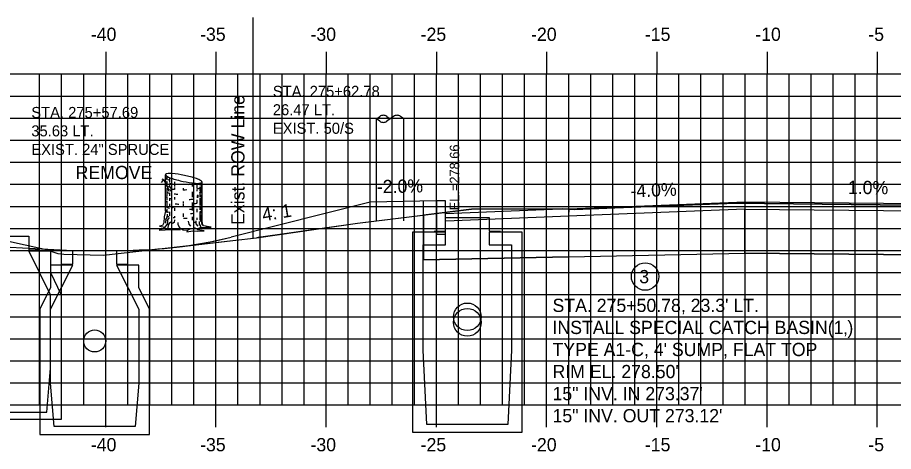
# Model space of a CAD drawing. Extents: x 853563 to 853733, y 366268 to 366378.
# Drawn here: x 853601.77 to 853641.5, y 366300.13 to 366319.79 of the extents above; entities that cross this region are included whole.
import ezdxf

# ---------------------------------------------------------------- set-up
doc = ezdxf.new("R2010")
doc.units = 0
for name, color, linetype in [('ANNOTATION', 7, 'Continuous'), ('D_Curb_Type1_Lt', 7, 'Continuous'), ('D_Drainage_CB_TypeA1-B1', 7, 'Continuous'), ('D_Drainage_Text', 7, 'Continuous'), ('D_Roadway_Edge_TW', 7, 'Continuous'), ('D_Roadway_FinishedGrade', 7, 'Continuous'), ('D_Roadway_SubGrade', 7, 'Continuous'), ('D_Text_Monospaced', 7, 'Continuous'), ('D_Text_Standard', 7, 'Continuous'), ('E_ROW_Line', 7, 'Continuous'), ('H_V ANNOTATION', 7, 'Continuous'), ('JUNK COM EXC', 7, 'Continuous'), ('JUNK FILL', 7, 'Continuous'), ('MAJOR', 7, 'Continuous'), ('MINOR', 7, 'Continuous'), ('PDRAIN', 7, 'Continuous'), ('S_Drainage_CB', 7, 'Continuous'), ('S_Roadway_Centerline', 7, 'Continuous'), ('S_Trees_Conifer_Pay', 7, 'Continuous'), ('S_Utilities_Pole_Power', 7, 'Continuous')]:
    doc.layers.add(name, color=color, linetype=linetype)

msp = doc.modelspace()

# ---------------------------------------------------------------- linework, layer by layer
at = {"layer": 'D_Curb_Type1_Lt'}
msp.add_lwpolyline([(853620.77, 366311.482), (853620.77, 366309.982), (853621.187, 366309.982), (853621.187, 366311.482)], close=True, dxfattribs=at)
at = {"layer": 'D_Drainage_CB_TypeA1-B1'}
for p, q in [((853620.169, 366310.067), (853619.677, 366310.067)), ((853619.677, 366310.067), (853619.677, 366300.996)), ((853621.187, 366310.067), (853620.169, 366310.067)), ((853624.172, 366310.067), (853623.155, 366310.067)), ((853624.664, 366310.067), (853624.172, 366310.067)), ((853624.664, 366300.996), (853624.664, 366310.067)), ((853603.266, 366308.571), (853603.266, 366307.554)), ((853603.266, 366306.57), (853604.283, 366308.571)), ((853604.283, 366308.571), (853603.266, 366308.571)), ((853607.269, 366308.571), (853606.252, 366308.571)), ((853606.252, 366308.571), (853607.269, 366306.57)), ((853607.269, 366307.554), (853607.269, 366308.571)), ((853620.169, 366304.719), (853620.169, 366308.065)), ((853624.172, 366308.065), (853624.172, 366304.719)), ((853603.266, 366307.554), (853602.774, 366306.57)), ((853607.761, 366306.57), (853607.269, 366307.554)), ((853602.774, 366306.57), (853602.774, 366300.894)), ((853603.266, 366303.224), (853603.266, 366306.57)), ((853607.269, 366306.57), (853607.269, 366303.224)), ((853607.761, 366300.894), (853607.761, 366306.57)), ((853620.334, 366301.356), (853620.169, 366304.719)), ((853624.172, 366304.719), (853624.008, 366301.356)), ((853603.43, 366301.255), (853603.266, 366303.224)), ((853607.269, 366303.224), (853607.105, 366301.255)), ((853624.008, 366301.356), (853620.334, 366301.356)), ((853602.774, 366300.894), (853607.761, 366300.894)), ((853607.105, 366301.255), (853603.43, 366301.255)), ((853619.677, 366300.996), (853624.664, 366300.996))]:
    msp.add_line(p, q, dxfattribs=at)
for points in [[(853620.662, 366310.108), (853621.187, 366310.108), (853621.187, 366310.732), (853623.155, 366310.732), (853623.155, 366310.108), (853623.68, 366310.108)], [(853620.169, 366308.065), (853620.169, 366309.49), (853621.187, 366309.49), (853621.187, 366310.067)], [(853623.155, 366310.067), (853623.155, 366309.49), (853624.172, 366309.49), (853624.172, 366308.065)], [(853603.758, 366308.613), (853604.283, 366308.613), (853604.283, 366309.236), (853606.252, 366309.236), (853606.252, 366308.613), (853606.777, 366308.613)]]:
    msp.add_lwpolyline(points, dxfattribs=at)
at = {"layer": 'D_Drainage_Text'}
msp.add_circle((853630.235, 366308.056), 0.625, dxfattribs=at)
at = {"layer": 'D_Roadway_Edge_TW'}
for p, q in [((853626.768, 366311.122), (853621.187, 366310.899)), ((853626.768, 366311.122), (853626.758, 366310.789)), ((853626.781, 366310.789), (853621.2, 366310.565))]:
    msp.add_line(p, q, dxfattribs=at)
msp.add_lwpolyline([(853626.768, 366311.122), (853634.768, 366311.442), (853645.768, 366311.343), (853656.768, 366311.123), (853664.768, 366310.803)], dxfattribs=at)
at = {"layer": 'D_Roadway_FinishedGrade'}
for p, q in [((853617.77, 366311.422), (853611.462, 366309.845)), ((853599.411, 366309.486), (853604.283, 366309.236)), ((853606.252, 366309.236), (853607.011, 366309.252))]:
    msp.add_line(p, q, dxfattribs=at)
msp.add_lwpolyline([(853620.77, 366311.482), (853617.77, 366311.422)], dxfattribs=at)
msp.add_arc((853606.611, 366329.248), 20, 271.1458, 284.0362, dxfattribs=at)
at = {"layer": 'D_Roadway_SubGrade'}
for p, q in [((853620.187, 366308.817), (853620.187, 366311.47)), ((853626.758, 366308.949), (853620.187, 366308.817))]:
    msp.add_line(p, q, dxfattribs=at)
for points in [[(853634.758, 366311.109), (853626.758, 366310.789), (853626.758, 366308.949), (853634.758, 366309.109)], [(853634.758, 366309.109), (853634.758, 366311.109), (853645.758, 366311.01), (853656.758, 366310.79), (853656.758, 366308.79), (853645.758, 366309.01)]]:
    msp.add_lwpolyline(points, close=True, dxfattribs=at)
at = {"layer": 'E_ROW_Line'}
msp.add_line((853612.463, 366309.794), (853612.463, 366319.794), dxfattribs=at)
at = {"layer": 'JUNK COM EXC'}
msp.add_lwpolyline([(853620.187, 366310.842), (853620.187, 366308.817), (853626.758, 366308.949), (853634.758, 366309.109), (853645.758, 366309.01), (853656.758, 366308.79), (853665.758, 366308.61), (853665.766, 366310.621), (853661.346, 366310.741), (853659.822, 366310.792), (853658.471, 366310.84), (853657.772, 366310.858), (853645.768, 366311.281), (853644.236, 366311.274), (853640.891, 366311.31), (853634.333, 366311.383), (853628.855, 366311.175), (853627.053, 366311.098), (853626.465, 366311.121), (853622.365, 366311.115), (853620.187, 366310.842)], dxfattribs=at)
at = {"layer": 'JUNK FILL'}
msp.add_lwpolyline([(853609.359, 366309.437), (853611.54, 366309.683), (853612.606, 366309.811), (853617.194, 366310.468), (853620.77, 366310.915), (853620.77, 366311.482), (853617.77, 366311.422), (853611.462, 366309.845)], dxfattribs=at)
msp.add_arc((853606.611, 366329.248), 20, 277.8984, 284.0362, dxfattribs=at)
at = {"layer": 'MAJOR'}
for p, q in [((853605.768, 366318.238), (853605.768, 366317.236)), ((853610.768, 366318.238), (853610.768, 366317.236)), ((853615.768, 366318.238), (853615.768, 366317.236)), ((853620.768, 366318.238), (853620.768, 366317.236)), ((853625.768, 366318.238), (853625.768, 366317.236)), ((853630.768, 366318.238), (853630.768, 366317.236)), ((853635.768, 366318.238), (853635.768, 366317.236)), ((853640.768, 366318.238), (853640.768, 366317.236)), ((853575.768, 366317.236), (853715.768, 366317.236)), ((853575.768, 366317.236), (853715.768, 366317.236)), ((853605.768, 366302.236), (853605.768, 366317.236)), ((853610.768, 366302.236), (853610.768, 366317.236)), ((853615.768, 366302.236), (853615.768, 366317.236)), ((853620.768, 366302.236), (853620.768, 366317.236)), ((853625.768, 366302.236), (853625.768, 366317.236)), ((853630.768, 366302.236), (853630.768, 366317.236)), ((853635.768, 366302.236), (853635.768, 366317.236)), ((853640.768, 366302.236), (853640.768, 366317.236)), ((853575.768, 366312.236), (853715.768, 366312.236)), ((853575.768, 366307.236), (853715.768, 366307.236)), ((853575.768, 366302.236), (853715.768, 366302.236)), ((853575.768, 366302.236), (853715.768, 366302.236)), ((853605.768, 366301.234), (853605.768, 366302.236)), ((853610.768, 366301.234), (853610.768, 366302.236)), ((853615.768, 366301.234), (853615.768, 366302.236)), ((853620.768, 366301.234), (853620.768, 366302.236)), ((853625.768, 366301.234), (853625.768, 366302.236)), ((853630.768, 366301.234), (853630.768, 366302.236)), ((853635.768, 366301.234), (853635.768, 366302.236)), ((853640.768, 366301.234), (853640.768, 366302.236))]:
    msp.add_line(p, q, dxfattribs=at)
at = {"layer": 'MINOR'}
for p, q in [((853602.768, 366302.236), (853602.768, 366317.236)), ((853603.768, 366302.236), (853603.768, 366317.236)), ((853604.768, 366302.236), (853604.768, 366317.236)), ((853606.768, 366302.236), (853606.768, 366317.236)), ((853607.768, 366302.236), (853607.768, 366317.236)), ((853608.768, 366302.236), (853608.768, 366317.236)), ((853609.768, 366302.236), (853609.768, 366317.236)), ((853611.768, 366302.236), (853611.768, 366317.236)), ((853612.768, 366302.236), (853612.768, 366317.236)), ((853613.768, 366302.236), (853613.768, 366317.236)), ((853614.768, 366302.236), (853614.768, 366317.236)), ((853616.768, 366302.236), (853616.768, 366317.236)), ((853617.768, 366302.236), (853617.768, 366317.236)), ((853618.768, 366302.236), (853618.768, 366317.236)), ((853619.768, 366302.236), (853619.768, 366317.236)), ((853621.768, 366302.236), (853621.768, 366317.236)), ((853622.768, 366302.236), (853622.768, 366317.236)), ((853623.768, 366302.236), (853623.768, 366317.236)), ((853624.768, 366302.236), (853624.768, 366317.236)), ((853626.768, 366302.236), (853626.768, 366317.236)), ((853627.768, 366302.236), (853627.768, 366317.236)), ((853628.768, 366302.236), (853628.768, 366317.236)), ((853629.768, 366302.236), (853629.768, 366317.236)), ((853631.768, 366302.236), (853631.768, 366317.236)), ((853632.768, 366302.236), (853632.768, 366317.236)), ((853633.768, 366302.236), (853633.768, 366317.236)), ((853634.768, 366302.236), (853634.768, 366317.236)), ((853636.768, 366302.236), (853636.768, 366317.236)), ((853637.768, 366302.236), (853637.768, 366317.236)), ((853638.768, 366302.236), (853638.768, 366317.236)), ((853639.768, 366302.236), (853639.768, 366317.236)), ((853575.768, 366316.236), (853715.768, 366316.236)), ((853575.768, 366315.236), (853715.768, 366315.236)), ((853575.768, 366314.236), (853715.768, 366314.236)), ((853575.768, 366313.236), (853715.768, 366313.236)), ((853575.768, 366311.236), (853715.768, 366311.236)), ((853575.768, 366310.236), (853715.768, 366310.236)), ((853575.768, 366309.236), (853715.768, 366309.236)), ((853575.768, 366308.236), (853715.768, 366308.236)), ((853575.768, 366306.236), (853715.768, 366306.236)), ((853575.768, 366305.236), (853715.768, 366305.236)), ((853575.768, 366304.236), (853715.768, 366304.236)), ((853575.768, 366303.236), (853715.768, 366303.236))]:
    msp.add_line(p, q, dxfattribs=at)
at = {"layer": 'PDRAIN'}
for centre, radius in [((853622.171, 366306.231), 0.625), ((853622.171, 366305.981), 0.625), ((853622.171, 366305.981), 0.625), ((853605.268, 366305.136), 0.5)]:
    msp.add_circle(centre, radius, dxfattribs=at)
at = {"layer": 'S_Drainage_CB'}
for p, q in [((853602.277, 366309.224), (853603.261, 366309.224)), ((853603.261, 366307.223), (853602.277, 366309.224)), ((853603.261, 366309.224), (853603.261, 366308.24)), ((853603.261, 366308.24), (853603.753, 366307.223)), ((853603.261, 366303.909), (853603.261, 366307.223)), ((853603.753, 366307.223), (853603.753, 366301.58)), ((853603.097, 366301.908), (853603.261, 366303.909)), ((853599.423, 366301.908), (853603.097, 366301.908)), ((853603.753, 366301.58), (853598.766, 366301.58))]:
    msp.add_line(p, q, dxfattribs=at)
msp.add_lwpolyline([(853599.784, 366309.266), (853600.276, 366309.266), (853600.276, 366309.889), (853602.277, 366309.889), (853602.277, 366309.266), (853602.769, 366309.266)], dxfattribs=at)
at = {"layer": 'S_Roadway_Centerline'}
msp.add_lwpolyline([(853601.219, 366309.683), (853603, 366309.295), (853603.592, 366309.1), (853603.865, 366309.076), (853605.661, 366309.021), (853611.54, 366309.683), (853612.606, 366309.811), (853612.705, 366309.838), (853617.194, 366310.468), (853622.365, 366311.115), (853626.465, 366311.121), (853627.053, 366311.098), (853628.855, 366311.175), (853634.333, 366311.383), (853640.891, 366311.31), (853644.236, 366311.274)], dxfattribs=at)
at = {"layer": 'S_Trees_Conifer_Pay'}
for p, q in [((853608.475, 366311.024), (853608.475, 366312.671)), ((853608.546, 366312.599), (853608.546, 366312.436)), ((853608.664, 366312.538), (853608.664, 366312.315)), ((853608.546, 366312.369), (853608.546, 366312.241)), ((853608.546, 366312.054), (853608.546, 366311.718)), ((853608.607, 366312.043), (853608.658, 366311.984)), ((853608.664, 366312.226), (853608.664, 366312.179)), ((853608.892, 366312.342), (853608.892, 366312.142)), ((853608.892, 366312.085), (853608.892, 366311.996)), ((853609.282, 366312.068), (853609.282, 366311.973)), ((853609.688, 366312.3), (853609.688, 366312.132)), ((853609.908, 366312.279), (853609.908, 366312.047)), ((853610.033, 366312.287), (853610.033, 366312.19)), ((853610.033, 366312.115), (853610.033, 366311.911)), ((853610.092, 366312.298), (853610.092, 366311.827)), ((853610.139, 366310.614), (853610.139, 366312.336)), ((853608.546, 366311.681), (853608.546, 366311.518)), ((853608.664, 366311.844), (853608.664, 366311.712)), ((853608.892, 366311.648), (853608.892, 366311.543)), ((853609.688, 366311.895), (853609.688, 366311.658)), ((853609.908, 366312.006), (853609.908, 366311.932)), ((853610.033, 366311.854), (853610.033, 366311.654)), ((853610.092, 366311.763), (853610.092, 366311.455)), ((853608.546, 366311.471), (853608.546, 366311.255)), ((853608.664, 366311.601), (853608.664, 366311.491)), ((853608.664, 366311.356), (853608.664, 366311.214)), ((853609.282, 366311.455), (853609.282, 366311.38)), ((853609.282, 366311.356), (853609.282, 366311.207)), ((853609.688, 366311.413), (853609.688, 366311.261)), ((853609.908, 366311.529), (853609.908, 366311.39)), ((853610.033, 366311.607), (853610.033, 366311.271)), ((853610.092, 366311.407), (853610.092, 366310.915)), ((853608.546, 366311.224), (853608.546, 366311.15)), ((853608.546, 366311.109), (853608.546, 366310.936)), ((853608.664, 366310.987), (853608.664, 366310.814)), ((853608.892, 366311.176), (853608.892, 366311.03)), ((853609.282, 366310.915), (853609.282, 366310.762)), ((853609.688, 366311.218), (853609.688, 366311.045)), ((853609.908, 366311.119), (853609.908, 366310.977)), ((853610.033, 366311.218), (853610.033, 366311.082)), ((853610.033, 366310.983), (853610.033, 366310.604)), ((853610.092, 366310.861), (853610.092, 366310.614)), ((853608.892, 366310.798), (853608.892, 366310.709)), ((853609.688, 366310.767), (853609.688, 366310.614)), ((853609.908, 366310.715), (853609.908, 366310.621)), ((853609.471, 366310.157), (853609.597, 366310.221)), ((853609.908, 366310.221), (853609.745, 366310.285))]:
    msp.add_line(p, q, dxfattribs=at)
for points in [[(853608.658, 366312.169), (853608.621, 366312.095), (853608.574, 366312.152), (853608.516, 366312.22), (853608.424, 366312.414), (853608.359, 366312.461), (853608.328, 366312.468)], [(853608.429, 366312.402), (853608.353, 366312.41), (853608.281, 366312.311)], [(853608.643, 366311.916), (853608.607, 366312.043), (853608.543, 366312.159), (853608.512, 366312.226), (853608.443, 366312.373)], [(853608.691, 366312.132), (853608.722, 366312.047), (853608.726, 366311.98), (853608.695, 366311.916)], [(853609.96, 366311.642), (853609.966, 366311.737), (853609.922, 366311.714), (853609.922, 366311.619)], [(853608.821, 366311.243), (853608.808, 366311.166), (853608.761, 366311.176), (853608.773, 366311.343)], [(853608.475, 366311.024), (853608.424, 366310.762), (853608.407, 366310.489), (853608.349, 366310.363), (853608.214, 366310.333), (853608.444, 366310.295), (853608.444, 366310.295), (853608.438, 366310.248), (853608.191, 366310.153), (853608.465, 366310.17), (853608.821, 366310.19), (853609.142, 366310.18), (853609.136, 366310.262), (853609.284, 366310.18), (853609.471, 366310.157), (853609.447, 366310.089), (853609.714, 366310.132), (853609.935, 366310.106), (853610.227, 366310.123), (853609.939, 366310.18), (853609.908, 366310.221), (853610.071, 366310.279), (853610.307, 366310.289), (853610.548, 366310.289), (853610.206, 366310.347), (853610.165, 366310.427), (853610.139, 366310.614)], [(853608.549, 366310.882), (853608.543, 366310.736), (853608.496, 366310.668), (853608.485, 366310.468)], [(853608.648, 366310.736), (853608.574, 366310.631), (853608.569, 366310.458), (853608.444, 366310.295)], [(853608.607, 366310.242), (853608.621, 366310.38), (853608.695, 366310.509)], [(853608.885, 366310.631), (853608.874, 366310.505), (853608.8, 366310.462)], [(853609.136, 366310.262), (853609.061, 366310.404), (853609.052, 366310.505)], [(853609.624, 366310.333), (853609.556, 366310.427), (853609.529, 366310.567)], [(853609.85, 366310.573), (853609.85, 366310.442), (853609.939, 366310.342)], [(853610.013, 366310.547), (853610.007, 366310.431), (853610.06, 366310.342), (853610.071, 366310.279)], [(853610.091, 366310.567), (853610.112, 366310.489), (853610.132, 366310.394)]]:
    msp.add_lwpolyline(points, dxfattribs=at)
for centre, radius, start, end in [((853608.497, 366312.671), 0.0226, 156.5926, 168.2806), ((853608.497, 366312.671), 0.0226, 168.2806, 179.9685), ((853608.501, 366312.671), 0.0264, 179.9685, 190.7806), ((853608.506, 366312.672), 0.0314, 190.7806, 203.4842), ((853608.508, 366312.545), 0.0334, 185.7849, 196.0515), ((853608.518, 366312.548), 0.0441, 196.0515, 210), ((853608.501, 366312.67), 0.0264, 145.7806, 156.5926), ((853608.526, 366312.681), 0.0527, 203.4842, 213.2806), ((853608.505, 366312.667), 0.0314, 133.077, 145.7806), ((853608.534, 366312.557), 0.0624, 210, 228.7494), ((853608.55, 366312.697), 0.0817, 213.2806, 227.6113), ((853608.519, 366312.651), 0.0527, 123.2806, 133.077), ((853608.535, 366312.627), 0.0817, 108.9499, 123.2806), ((853608.606, 366312.64), 0.172, 228.7494, 240), ((853608.664, 366312.821), 0.251, 227.6113, 235.7806), ((853608.59, 366312.468), 0.251, 100.7806, 108.9499), ((853608.973, 366313.277), 0.802, 235.7806, 251.9406), ((853608.693, 366311.926), 0.802, 84.6206, 100.7806), ((853608.806, 366312.985), 0.571, 247.5868, 255.5683), ((853610.33, 366317.439), 5.179, 251.9406, 258.2806), ((853608.283, 366307.568), 5.179, 78.2806, 84.6206), ((853608.283, 366307.568), 5.179, 71.9406, 78.2806), ((853609.64, 366311.73), 0.802, 55.7806, 71.9406), ((853608.508, 366312.391), 0.0334, 185.7849, 196.0515), ((853608.518, 366312.393), 0.0441, 196.0515, 210), ((853608.534, 366312.403), 0.0624, 210, 228.7494), ((853608.606, 366312.485), 0.172, 228.7494, 240), ((853608.806, 366312.83), 0.571, 240, 242.9763), ((853608.806, 366312.83), 0.571, 255.6333, 261.8968), ((853609.307, 366316.348), 4.124, 261.8968, 263.762), ((853609.308, 366316.115), 4.124, 262.9442, 264.2151), ((853610.33, 366317.439), 5.179, 258.2806, 264.6206), ((853609.307, 366316.348), 4.124, 273.2669, 275.3045), ((853609.92, 366313.081), 0.802, 264.6206, 280.7806), ((853609.809, 366312.597), 0.571, 282.0154, 293.1403), ((853610.023, 366312.539), 0.251, 280.7806, 288.9499), ((853609.95, 366312.186), 0.251, 47.6113, 55.7806), ((853609.809, 366312.597), 0.571, 299.6633, 300), ((853610.008, 366312.252), 0.172, 300, 311.2506), ((853610.078, 366312.38), 0.0817, 288.9499, 303.2806), ((853610.064, 366312.31), 0.0817, 33.2806, 47.6113), ((853610.08, 366312.17), 0.0624, 311.2506, 330), ((853610.094, 366312.355), 0.0527, 303.2806, 313.077), ((853610.108, 366312.34), 0.0314, 313.077, 325.7806), ((853610.088, 366312.326), 0.0527, 23.4842, 33.2806), ((853610.113, 366312.337), 0.0264, 325.7806, 336.5926), ((853610.096, 366312.161), 0.0441, 330, 343.9485), ((853610.107, 366312.335), 0.0314, 10.7806, 23.4842), ((853610.116, 366312.336), 0.0226, 336.5926, 348.2806), ((853610.112, 366312.336), 0.0264, 359.9685, 10.7806), ((853610.116, 366312.336), 0.0226, 348.2806, 359.9685), ((853610.107, 366312.158), 0.0334, 0, 16.0515), ((853610.107, 366312.158), 0.0334, 343.9485, 360), ((853608.508, 366311.947), 0.0334, 185.7849, 196.0515), ((853608.509, 366311.711), 0.0334, 185.7849, 196.0515), ((853608.52, 366311.714), 0.0441, 196.0515, 210), ((853608.535, 366311.723), 0.0624, 210, 228.7494), ((853608.608, 366311.806), 0.172, 228.7494, 240), ((853608.807, 366312.151), 0.571, 240, 242.8104), ((853608.806, 366312.386), 0.571, 242.9571, 255.5507), ((853609.307, 366315.904), 4.124, 264.0496, 266.2948), ((853609.308, 366316.115), 4.124, 269.6419, 270), ((853609.308, 366316.115), 4.124, 270, 271.9249), ((853609.807, 366312.386), 0.571, 292.9413, 300), ((853609.809, 366312.151), 0.571, 299.6633, 300), ((853610.008, 366311.806), 0.172, 300, 311.2506), ((853610.08, 366311.723), 0.0624, 311.2506, 330), ((853610.096, 366311.714), 0.0441, 330, 343.9485), ((853610.107, 366311.711), 0.0334, 0, 16.0515), ((853610.107, 366311.711), 0.0334, 343.9485, 360), ((853608.509, 366311.501), 0.0334, 185.7849, 196.0515), ((853608.52, 366311.504), 0.0441, 196.0515, 210), ((853608.535, 366311.513), 0.0624, 210, 228.7494), ((853608.608, 366311.596), 0.172, 228.7494, 240), ((853608.807, 366311.941), 0.571, 240, 242.8104), ((853608.807, 366312.151), 0.571, 253.0704, 261.8968), ((853609.308, 366315.668), 4.124, 261.8968, 262.3875), ((853609.308, 366315.458), 4.124, 264.5431, 266.8507), ((853609.308, 366315.458), 4.124, 269.6419, 270), ((853609.308, 366315.668), 4.124, 273.3324, 275.919), ((853609.308, 366315.458), 4.124, 276.8526, 278.1032), ((853609.809, 366311.941), 0.571, 278.1032, 280.7293), ((853609.809, 366311.941), 0.571, 293.1403, 300), ((853610.008, 366311.596), 0.172, 300, 311.2506), ((853610.008, 366311.359), 0.172, 300, 311.2506), ((853610.08, 366311.513), 0.0624, 311.2506, 330), ((853610.08, 366311.276), 0.0624, 311.2506, 330), ((853610.096, 366311.504), 0.0441, 330, 343.9485), ((853610.096, 366311.267), 0.0441, 330, 343.9485), ((853610.107, 366311.501), 0.0334, 0, 16.0515), ((853610.107, 366311.501), 0.0334, 343.9485, 360), ((853610.107, 366311.264), 0.0334, 0, 16.0515), ((853610.107, 366311.264), 0.0334, 343.9485, 360), ((853608.509, 366311.066), 0.0334, 185.7849, 196.0515), ((853608.52, 366311.069), 0.0441, 196.0515, 210), ((853608.535, 366311.078), 0.0624, 210, 228.7494), ((853608.608, 366311.161), 0.172, 228.7494, 240), ((853608.807, 366311.506), 0.571, 240, 250.7093), ((853608.807, 366311.704), 0.571, 242.8104, 254.6017), ((853609.308, 366315.221), 4.124, 273.6807, 275.284), ((853609.308, 366315.024), 4.124, 274.1603, 276.5009), ((853609.809, 366311.704), 0.571, 293.1403, 300), ((853609.82, 366311.512), 0.571, 291.9732, 298.7631), ((853610.008, 366310.965), 0.172, 300, 311.2506), ((853610.08, 366310.883), 0.0624, 311.2506, 330), ((853610.096, 366310.874), 0.0441, 330, 343.9485), ((853610.107, 366311.066), 0.0334, 0, 16.0515), ((853610.107, 366310.871), 0.0334, 0, 16.0515), ((853610.107, 366310.871), 0.0334, 343.9485, 360), ((853608.509, 366310.65), 0.0334, 185.7849, 196.0515), ((853608.52, 366310.653), 0.0441, 196.0515, 210), ((853608.535, 366310.663), 0.0624, 210, 228.7494), ((853608.608, 366310.745), 0.172, 228.7494, 240), ((853608.807, 366311.311), 0.571, 242.7279, 251.4933), ((853608.807, 366311.09), 0.571, 258.363, 261.8968), ((853609.308, 366314.608), 4.124, 261.8968, 262.6316), ((853609.308, 366314.828), 4.124, 263.2104, 264.2151), ((853609.308, 366314.828), 4.124, 269.8672, 270), ((853609.308, 366314.828), 4.124, 270, 272.1883), ((853609.308, 366314.608), 4.124, 276.488, 277.5562), ((853609.809, 366311.311), 0.571, 293.1403, 300), ((853609.809, 366311.09), 0.571, 295.4686, 300), ((853610.008, 366310.745), 0.172, 300, 311.2506), ((853610.08, 366310.663), 0.0624, 311.2506, 330), ((853610.096, 366310.653), 0.0441, 330, 343.9485), ((853610.107, 366310.65), 0.0334, 0, 16.0515), ((853610.107, 366310.65), 0.0334, 343.9485, 360)]:
    msp.add_arc(centre, radius, start, end, dxfattribs=at)
at = {"layer": 'S_Utilities_Pole_Power'}
for p, q in [((853618.044, 366315.203), (853618.2, 366315.314)), ((853618.044, 366310.584), (853618.047, 366315.203)), ((853618.2, 366315.093), (853618.044, 366315.203)), ((853618.513, 366315.314), (853618.669, 366315.203)), ((853618.669, 366315.203), (853618.513, 366315.093)), ((853618.826, 366315.314), (853618.669, 366315.203)), ((853619.294, 366315.203), (853619.138, 366315.314)), ((853619.294, 366310.584), (853619.297, 366315.203))]:
    msp.add_line(p, q, dxfattribs=at)
for centre, start, end in [((853618.357, 366315.093), 90, 125.2644), ((853618.357, 366315.093), 54.7356, 90), ((853618.982, 366315.093), 90, 125.2644), ((853618.982, 366315.093), 54.7356, 90), ((853618.357, 366315.314), 234.7356, 270), ((853618.357, 366315.314), 270, 305.2644)]:
    msp.add_arc(centre, 0.271, start, end, dxfattribs=at)

# ---------------------------------------------------------------- texts
at = {"layer": 'ANNOTATION'}
msp.add_text('REMOVE', height=0.6, dxfattribs=at).set_placement((853604.404, 366312.472))
for s, rotation, p in [('-2.0%', 1.1458, (853618.073, 366311.828)), ('-4.0%', 2.2906, (853629.583, 366311.635)), ('1.0%', 359.4872, (853639.431, 366311.8)), ('4: 1', 9.4623, (853612.915, 366310.556))]:
    msp.add_text(s, height=0.6, rotation=rotation, dxfattribs=at).set_placement(p)
at = {"layer": 'D_Drainage_Text'}
for s, p in [("STA. 275+50.78, 23.3' LT.", (853626.035, 366306.45)), ('INSTALL SPECIAL CATCH BASIN(1‚)', (853626.035, 366305.45)), ("TYPE A1-C, 4' SUMP, FLAT TOP", (853626.035, 366304.45)), ("RIM EL. 278.50'", (853626.035, 366303.45)), ('15" INV. IN 273.37\'', (853626.035, 366302.45)), ('15" INV. OUT 273.12\'', (853626.035, 366301.45))]:
    msp.add_text(s, height=0.6, dxfattribs=at).set_placement(p)
at = {"layer": 'D_Text_Monospaced'}
for s, height, p in [('STA. 275+62.78', 0.49998, (853613.348, 366316.2)), ('STA. 275+57.69', 0.49998, (853602.393, 366315.242)), ('26.47 LT.', 0.5, (853613.348, 366315.366)), ('35.63 LT.', 0.5, (853602.393, 366314.408)), ('EXIST. 50/S', 0.49998, (853613.348, 366314.526)), ('EXIST. 24" SPRUCE', 0.49998, (853602.393, 366313.568))]:
    msp.add_text(s, height=height, dxfattribs=at).set_placement(p)
at = {"layer": 'D_Text_Standard'}
msp.add_text(' EL.=278.66', height=0.4335, rotation=90, dxfattribs=at).set_placement((853621.807, 366310.897))
at = {"layer": 'E_ROW_Line'}
msp.add_text('Exist. ROW Line', height=0.6, rotation=90, dxfattribs=at).set_placement((853612.063, 366310.394))
at = {"layer": 'H_V ANNOTATION'}
for s, p in [('-40', (853605.093, 366318.736)), ('-35', (853610.048, 366318.736)), ('-30', (853615.056, 366318.736)), ('-25', (853620.053, 366318.736)), ('-20', (853625.061, 366318.736)), ('-15', (853630.224, 366318.736)), ('-10', (853635.232, 366318.736)), ('-5', (853640.358, 366318.736)), ('3', (853629.969, 366307.752)), ('-40', (853605.093, 366300.136)), ('-35', (853610.048, 366300.136)), ('-30', (853615.056, 366300.136)), ('-25', (853620.053, 366300.136)), ('-20', (853625.061, 366300.136)), ('-15', (853630.224, 366300.136)), ('-10', (853635.232, 366300.136)), ('-5', (853640.358, 366300.136))]:
    msp.add_text(s, height=0.6, dxfattribs=at).set_placement(p)

doc.saveas('drawing.dxf')
